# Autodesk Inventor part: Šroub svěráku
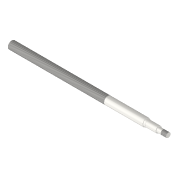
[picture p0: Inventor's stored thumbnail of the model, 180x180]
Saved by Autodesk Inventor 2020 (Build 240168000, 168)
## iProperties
Created: 2025-03
Part Number: Šroub svěráku
Material: Ocel
Document SubType Name: Modeling
Designer: doma
Density: 7.85 g/cm^3
Appearance: Ocel
Mass: 933.179 g
Surface Area: 251.672 cm^2
Volume: 118.876 cm^3
Author: doma
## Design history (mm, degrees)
sketch "Náčrt1"
  geometry: L1 (-350, 10)-(-350, 0); L2 (-350, 10)-(0, 10); L3 (-350, 0)-(57, 0); L4 (0, 10)-(0, 8.5); L5 (0, 8.5)-(5, 8.5); L6 (5, 8.5)-(5, 8); L7 (5, 8)-(32, 8); L8 (32, 8)-(32, 6); L9 (32, 6)-(57, 6); L10 (57, 6)-(57, 0); 1 further point
  constraints: 20 end point, 3 horizontal, 3 vertical, 2 perpendicular, 1 parallel, 1 point on line
  dimensions: "d0" = 10 distance of L1.start L1.end; "d14" = 8.5 distance between parallel lines of L3 L5; "d15" = 5 distance of L4.end L5.end; "d19" = 350 distance of L1.start L2.end; "d25" = 8 distance between parallel lines of L3 L7; "d26" = 27 distance of L6.end L7.end; "d27" = 6 distance between parallel lines of L3 L9; "d28" = 25 distance of L8.end L9.end
revolve "Rotace1" sketch "Náčrt1" stored, may be unused: angle "d20" = 90 deg
feature "Závit1" dims "d21" = 250, "d22" = 0
feature "Závit3" dims "d29" = 14, "d30" = 0
node "Pracovní rovina1"
  node "Pracovní bod1"
sketch "Náčrt2"
  geometry: L1 (0, 0)-(-5, 0); 2 further points
  constraints: 2 end point, 1 coincident, 1 horizontal
  dimensions: "d31" = 5 distance of L1.start L1.end
hole "Díra1" sketch "Náčrt2" at (-5, 0) diameter "d32" = 3.242; stored, may be unused: countersink angle "d36" = 90 deg, drill point angle "d38" = 118 deg; dims "d33" = 5, "d34" = 4, "d35" = 2, "d37" = 8
node "Těleso1"
